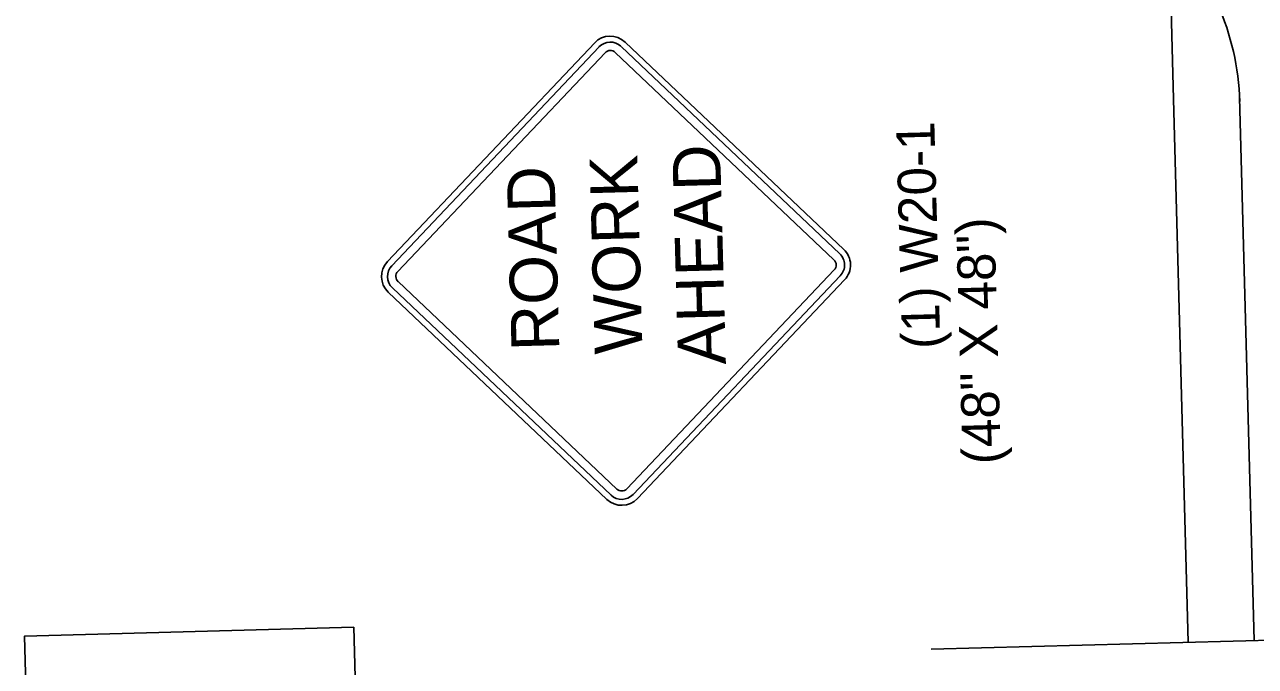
# Model space of a CAD drawing. Extents: x 1929653 to 1931621, y 596452 to 600944.
# Drawn here: x 1930655.2 to 1930944.7, y 597219.5 to 597370.4 of the extents above; entities that cross this region are included whole.
import ezdxf

# ---------------------------------------------------------------- set-up
doc = ezdxf.new("R2010")
doc.units = 0
for name, color, linetype in [('P_TC_Signs_Temporary', 7, 'Continuous'), ('R_Border', 7, 'Continuous'), ('R_Draft', 7, 'Continuous')]:
    doc.layers.add(name, color=color, linetype=linetype)

msp = doc.modelspace()

# ---------------------------------------------------------------- linework, layer by layer
at = {"layer": 'P_TC_Signs_Temporary'}
for p, q in [((1930789.3, 597366.11), (1930740.55, 597314.67)), ((1930790.32, 597365.14), (1930741.57, 597313.7)), ((1930846.93, 597316.53), (1930795.49, 597365.28)), ((1930847.9, 597317.55), (1930796.46, 597366.3)), ((1930791.75, 597363.79), (1930743, 597312.34)), ((1930845.58, 597315.1), (1930794.14, 597363.85)), ((1930796.89, 597261.27), (1930845.64, 597312.71)), ((1930743.06, 597309.96), (1930794.5, 597261.2)), ((1930798.32, 597259.91), (1930847.07, 597311.36)), ((1930799.34, 597258.95), (1930848.09, 597310.39)), ((1930740.74, 597307.51), (1930792.18, 597258.76)), ((1930741.71, 597308.53), (1930793.15, 597259.78))]:
    msp.add_line(p, q, dxfattribs=at)
for centre, radius, start, end in [((1930792.97, 597362.63), 5.06, 46.5377, 136.5377), ((1930792.97, 597362.63), 3.66, 46.5377, 136.5377), ((1930792.97, 597362.63), 1.69, 46.5377, 136.5377), ((1930844.42, 597313.87), 3.66, 316.5377, 46.5377), ((1930844.42, 597313.87), 5.06, 316.5377, 46.5377), ((1930744.22, 597311.18), 5.06, 136.5377, 226.5377), ((1930744.22, 597311.18), 3.66, 136.5377, 226.5377), ((1930844.42, 597313.87), 1.69, 316.5377, 46.5377), ((1930744.22, 597311.18), 1.69, 136.5377, 226.5377), ((1930795.66, 597262.43), 1.69, 226.5377, 316.5377), ((1930795.66, 597262.43), 5.06, 226.5377, 316.5377), ((1930795.66, 597262.43), 3.66, 226.5377, 316.5377)]:
    msp.add_arc(centre, radius, start, end, dxfattribs=at)
at = {"layer": 'R_Border'}
msp.add_lwpolyline([(1930660.57, 597026.7), (1930655.21, 597226.62), (1930732.63, 597228.7), (1930738, 597028.77)], close=True, dxfattribs=at)
at = {"layer": 'R_Draft'}
for p, q in [((1930900.94, 598265.48), (1930925.44, 597352.83)), ((1930940.99, 597353.25), (1930944.42, 597225.58)), ((1930925.44, 597352.83), (1930928.86, 597225.16)), ((1930975.33, 597226.41), (1930868.47, 597223.54))]:
    msp.add_line(p, q, dxfattribs=at)
msp.add_arc((1930881.04, 597350.73), 60, 1.5377, 91.5377, dxfattribs=at)

# ---------------------------------------------------------------- texts
at = {"layer": 'P_TC_Signs_Temporary'}
for s, p in [(' AHEAD ', (1930820.28, 597286.35)), ('WORK', (1930800.56, 597293.08)), (' ROAD ', (1930781.11, 597289.63))]:
    msp.add_text(s, height=11.25, rotation=91.5377, dxfattribs=at).set_placement(p)
at = {"layer": 'R_Border'}
for s, p in [('(1) W20-1', (1930870.62, 597294.24)), ('(48" X 48")', (1930884.85, 597267.12))]:
    msp.add_text(s, height=9, rotation=91.5377, dxfattribs=at).set_placement(p)

doc.saveas('drawing.dxf')
